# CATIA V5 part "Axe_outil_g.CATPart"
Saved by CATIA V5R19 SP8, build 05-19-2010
Part number: Bras_g
Bounding box of the stored display mesh (mm): x -50 to 50, y -270 to 50, z -250 to 30
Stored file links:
  G:\EU_thinkMotion\CFAO_2010\MMS_groupe1\MMS_groupe1\OK\vduret\vduret\CATIA\Axe_outil_g.CATPart
  F:\CFAO TP\Machine_de_coupe.CATProduct
  G:\EU_thinkMotion\CFAO_2010\MMS_groupe1\MMS_groupe1\OK\vduret\vduret\CATIA\Bras_d.CATPart
  G:\EU_thinkMotion\CFAO_2010\MMS_groupe1\MMS_groupe1\OK\vduret\vduret\CATIA\Axe.CATPart
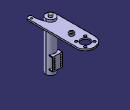
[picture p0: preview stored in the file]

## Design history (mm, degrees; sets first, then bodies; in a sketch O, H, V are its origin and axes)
Parameters
  Hauteur_bras = 200 mm
External parameters (linked from other documents)
  External.Longueur_axe_couronne = 200 mm
Body1 (main body)
  Sketch1 on xy-plane, origin (0, 0, 0), H (1, 0, 0), V (0, 1, 0)
    arc A1 centre (0, 0) radius 50 from (50, 0) to (-50, 0) ccw
    point P1 (-50, 0)
    line L1 (-50, 0) -> (-50, -200)
    arc A2 centre (-12.5, -200) radius 25 from (12.5, -200) to (-37.5, -200) ccw
    point P3 (-12.5, -200)
    line L2 (50, 0) -> (50, -270)
    point P4 (50, 0)
    line L3 (50, -270) -> (25, -270)
    line L4 (25, -270) -> (25, -235)
    line L5 (-50, -200) -> (-37.5, -200)
    line L6 (25, -235) -> (12.5, -200)
    point P9 (12.5, -200)
    construction line L7 (-200, -200) -> (290, -200)
    point P10 (-200, -200)
    circle A3 centre (37.5, -252.5) radius 5
    point P12 (37.5, -252.5)
    circle A4 centre (0, 0) radius 25
    construction line L8 (-116.0265, 0) -> (243.9735, 0)
    point P13 (-116.0265, 0)
    axis line L9 (0, -80) -> (0, 120)
    point P15 (0, -80)
    circle A5 centre (-25, 25) radius 7
    point P17 (-25, 25)
    circle A6 centre (25, 25) radius 7
    circle A7 centre (-25, -25) radius 7
    circle A8 centre (25, -25) radius 7
    circle A9 centre (5, -70) radius 7
    point P21 (5, -70)
    radius A1 = 50
    distance H L3 = 270 {= Hauteur_bras +70mm}
    length L4 = 35
    length L3 = 25
    radius A2 = 25
    distance P3 H = 200 {= Hauteur_bras}
    distance P3 L1 = 37.5
    length L1 = 200 {= Hauteur_bras}
    radius A3 = 5
    distance P12 L3 = 17.5
    distance P12 L2 = 12.5
    radius A4 = 25
    radius A5 = 7
    distance P17 L8 = 25
    distance P17 L9 = 25
    distance L9 P21 = 5
    distance P21 L8 = 70
    radius A9 = 7
    coincidence: P1 H, P4 H, P10 L5, P9 L7, P13 H, P15 V
    tangency: L1 A1, L2 A1
    horizontal: L3 H, L5 H, L7 H, L8 H
    vertical: L4 V, L9 V
    symmetry: A5 A6 L9, A5 A7 L8, A6 A8 L8
  Pad1: profile Sketch1, direction (0, 0, 1), length 8
  Fillet1: radius 20, on edge [face of Pad1 from Sketch1.L4 | face of Pad1 from Sketch1.L6]
  Fillet2: radius 9, on edge [face of Pad1 from Sketch1.L3 | face of Pad1 from Sketch1.L4]; edge [face of Pad1 from Sketch1.L2 | face of Pad1 from Sketch1.L3]
  Sketch2 on xy-plane, origin (0, 0, 0), H (1, 0, 0), V (0, 1, 0)
    circle A1 centre (-12.5, -200) radius 25
    reference projected arc E1 centre (-12.5, -200) radius 25 from (12.5, -200) to (-37.5, -200) ccw from edge [face of Pad1 from Sketch1.A2 | end face of Pad1]
    coincidence: A1 E1
  Pad2: profile Sketch2, direction (0, 0, 1), length 20, opposite side length 240 {= External.Longueur_axe_couronne +40mm}
  Sketch3 on end face of Pad2, origin (0, 0, 20), H (1, 0, 0), V (0, 1, 0)
    circle A1 centre (-12.5, -200) radius 10
    reference projected circle E1 centre (-12.5, -200) radius 25 from edge [face of Pad2 from Sketch2.A1 | end face of Pad2]
    radius A1 = 10
    concentricity: A1 E1
  Pad3: profile Sketch3, direction (0, 0, 1), length 10
  Sketch4 on start face of Pad2, origin (0, 0, -240), H (1, 0, 0), V (0, -1, 0)
    circle A1 centre (-12.5, 200) radius 10
    point P1 (-12.5, 200)
    reference projected circle E1 centre (-12.5, 200) radius 25 from edge [start face of Pad2 | face of Pad2 from Sketch2.A1]
    radius A1 = 10
    concentricity: P1 E1
  Pad4: profile Sketch4, direction (0, 0, -1), length 10
  Point1: type Center, Curve edge [start face of Pad2 | face of Pad4 from Sketch4.A1]
  Plane1: type OffsetPt, RefPlane yz-plane, RefPoint Point1
  Sketch5 on Plane1, origin (-12.5, 0, 0), H (0, 1, 0), V (0, 0, 1)
    line L1 (-184, -140) -> (-162, -140)
    line L2 (-162, -140) -> (-162, -210)
    line L3 (-162, -210) -> (-184, -210)
    line L4 (-184, -210) -> (-184, -206)
    line L5 (-184, -206) -> (-166, -206)
    line L6 (-166, -206) -> (-166, -144)
    line L7 (-166, -144) -> (-184, -144)
    point P8 (-184, -144)
    line L8 (-184, -144) -> (-184, -140)
    reference projected line E1 (-225, -240) -> (-175, -240) from edge [start face of Pad2 | face of Pad2 from Sketch2.A1]
    reference projected line E2 through (-200, 0) direction (0, 1) from axis of face of Pad2 from Sketch2.A1
    distance L3 E1 = 30
    distance L5 L3 = 4
    distance L6 L2 = 4
    distance L7 L1 = 4
    distance L8 E2 = 16
    length L2 = 70
    length L1 = 22
    horizontal: L1 H, L3 H, L5 H, L7 H
    vertical: L2 V, L4 V, L6 V, L8 V
    coincidence: P8 L4
  Pad5: profile Sketch5, direction (1, 0, 0), length 25, mirrored extent
  Sketch6 on face of Pad5 from Sketch5.L2, origin (0, -162, 0), H (-1, 0, 0), V (0, 0, 1)
    construction line L1 (12.5, -360) -> (12.5, -490)
    reference projected line E1 (-12.5, -450) -> (-12.5, -380) from edge [face of Pad5 from Sketch5.L2 | end face of Pad5]
    construction line L2 (-50, -175) -> (90, -175)
    reference projected line E2 (37.5, -140) -> (-12.5, -140) from edge [face of Pad5 from Sketch5.L1 | face of Pad5 from Sketch5.L2]
    circle A1 centre (-3.5, -160) radius 3
    point P5 (-3.5, -160)
    point P6 (-3.5, -170)
    circle A2 centre (-3.5, -170) radius 3
    point P7 (-3.5, -150)
    circle A3 centre (-3.5, -150) radius 3
    reference projected line E3 (37.5, -140) -> (-12.5, -140) from edge [face of Pad5 from Sketch5.L1 | face of Pad5 from Sketch5.L2]
    axis line L3 (-3.5, -370) -> (-3.5, -460)
    circle A4 centre (-3.5, -200) radius 3
    circle A5 centre (-3.5, -190) radius 3
    circle A6 centre (-3.5, -180) radius 3
    circle A7 centre (28.5, -150) radius 3
    circle A8 centre (28.5, -160) radius 3
    circle A9 centre (28.5, -170) radius 3
    circle A10 centre (28.5, -180) radius 3
    circle A11 centre (28.5, -190) radius 3
    circle A12 centre (28.5, -200) radius 3
    distance L1 E1 = 25
    distance L2 E2 = 35
    radius A1 = 3
    distance P7 E3 = 10
    distance P7 P5 = 10
    distance P5 P6 = 10
    radius A3 = 3
    radius A1 = 3 (reference)
    radius A2 = 3
    distance L3 L1 = 16
    vertical: L1 V, L3 V
    horizontal: L2 H
    coincidence: P5 L3, P6 L3, L3 P7
    symmetry: A3 A4 L2, A1 A5 L2, A2 A6 L2, A3 A7 L1, A1 A8 L1, A2 A9 L1, A6 A10 L1, A5 A11 L1, A4 A12 L1
  Pocket1: profile Sketch6, direction (0, -1, 0), through (limit type 6)
  Sketch7 on start face of Pad1, origin (0, 0, 0), H (1, 0, 0), V (0, -1, 0)
    circle A1 centre (37.5, 252.5) radius 5
    circle A2 centre (37.5, 252.5) radius 7.5
    reference projected circle E1 centre (37.5, 252.5) radius 5 from edge [face of Pad1 from Sketch1.A3 | start face of Pad1]
    radius A2 = 7.5
    coincidence: A1 E1
  Pad6: profile Sketch7, direction (0, 0, -1), length 7
  Sketch8 on end face of Pad1, origin (0, 0, 8), H (1, 0, 0), V (0, 1, 0)
    circle A1 centre (5, -70) radius 12.5
    circle A2 centre (5, -70) radius 7
    reference projected circle E1 centre (5, -70) radius 7 from edge [end face of Pad1 | face of Pad1 from Sketch1.A9]
    radius A1 = 12.5
    coincidence: A2 E1
  Pad7: profile Sketch8, direction (0, 0, 1), length 10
